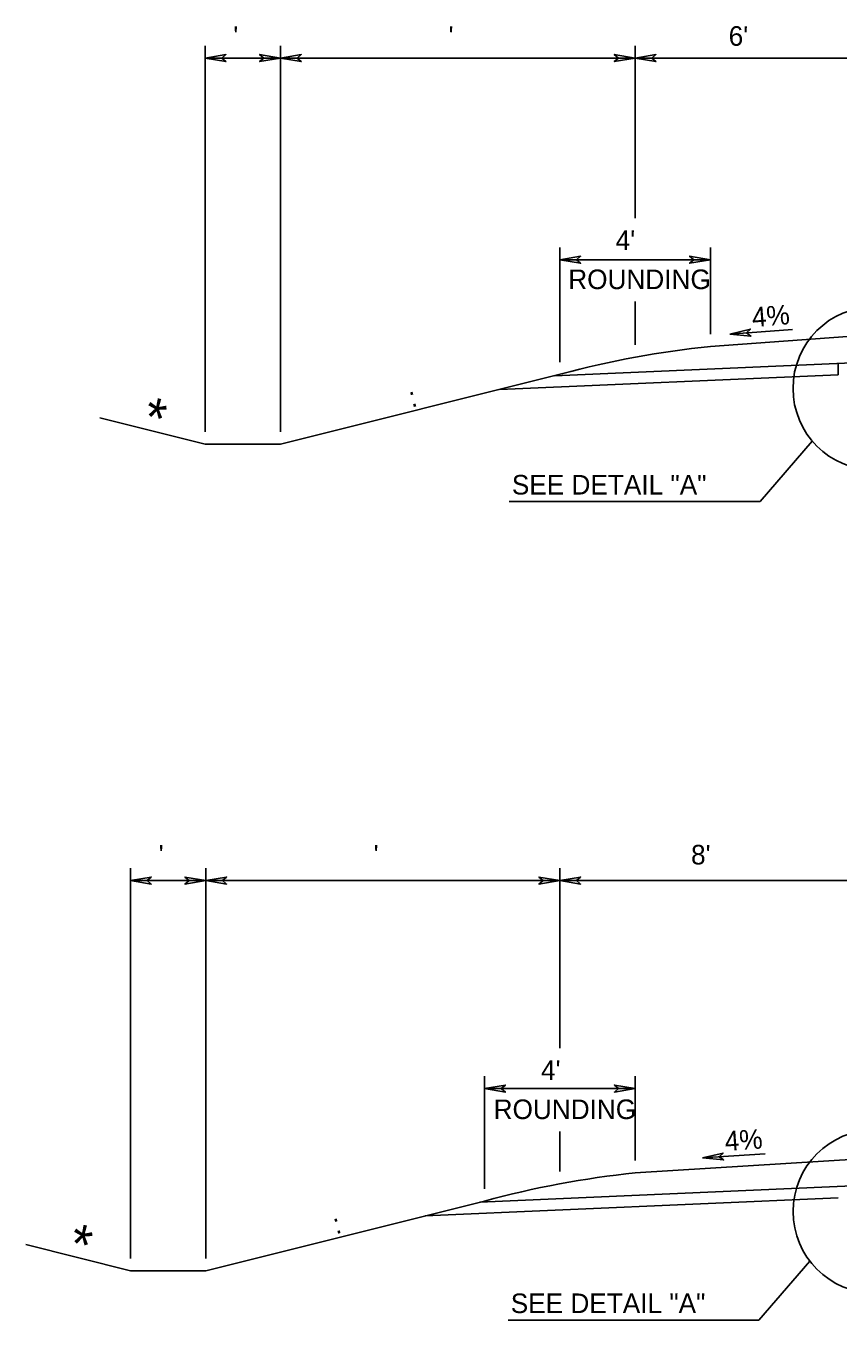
# Model space of a CAD drawing. Extents: x -540 to 1231, y -564 to 421.
# Drawn here: x -360 to -302, y 131.6 to 224.2 of the extents above; entities that cross this region are included whole.
import ezdxf

# ---------------------------------------------------------------- set-up
doc = ezdxf.new("R2010")
doc.units = 0
doc.layers.add('1', color=7, linetype='Continuous')
doc.layers.add('Des_ Drain_ Ftrs', color=7, linetype='Continuous')

msp = doc.modelspace()

# ---------------------------------------------------------------- linework, layer by layer
at = {"layer": '1'}
for p, q in [((-347.236, 195.118), (-347.236, 222.729)), ((-341.847, 195.118), (-341.847, 222.729)), ((-316.483, 210.408), (-316.483, 222.729)), ((-341.847, 221.849), (-347.236, 221.849)), ((-316.483, 221.849), (-341.847, 221.849)), ((-300.318, 221.849), (-316.483, 221.849)), ((-321.871, 200.111), (-321.871, 208.312)), ((-311.095, 202.117), (-311.095, 208.312)), ((-311.095, 207.432), (-321.871, 207.432)), ((-316.483, 201.34), (-316.483, 204.45)), ((-311.093, 201.238), (-300.327, 202.012)), ((-309.705, 202.115), (-305.219, 202.443)), ((-322.243, 199.138), (-273.377, 201.272)), ((-301.965, 200.022), (-301.965, 199.215)), ((-321.743, 199.263), (-341.847, 194.238)), ((-326.165, 198.158), (-301.965, 199.215)), ((-354.771, 196.122), (-347.236, 194.238)), ((-307.55, 190.143), (-303.81, 194.463)), ((-341.847, 194.238), (-347.236, 194.238)), ((-325.482, 190.143), (-307.55, 190.143)), ((-352.571, 136.034), (-352.571, 163.927)), ((-347.183, 136.034), (-347.183, 163.927)), ((-321.869, 151.054), (-321.869, 163.927)), ((-347.183, 163.047), (-352.571, 163.047)), ((-321.869, 163.047), (-347.183, 163.047)), ((-300.315, 163.047), (-321.869, 163.047)), ((-327.246, 141.018), (-327.246, 149.059)), ((-316.47, 143.027), (-316.47, 149.059)), ((-316.47, 148.179), (-327.246, 148.179)), ((-321.869, 142.248), (-321.869, 145.117)), ((-311.66, 143.227), (-307.171, 143.512)), ((-316.47, 142.147), (-300.32, 143.163)), ((-327.575, 140.056), (-273.374, 142.422)), ((-327.246, 140.138), (-347.183, 135.154)), ((-331.5, 139.074), (-301.962, 140.365)), ((-360.048, 137.023), (-352.571, 135.154)), ((-347.183, 135.154), (-352.571, 135.154)), ((-307.629, 131.623), (-303.981, 135.837)), ((-325.56, 131.623), (-307.629, 131.623))]:
    msp.add_line(p, q, dxfattribs=at)
for centre in [(-299.353, 198.235), (-299.35, 139.385)]:
    msp.add_circle(centre, 5.838, dxfattribs=at)
for centre, end in [((-304.211, 134.403), 105.12625), ((-309.587, 75.312), 105.23809)]:
    msp.add_arc(centre, 67.188, 95.87953, end, dxfattribs=at)
at = {"layer": 'Des_ Drain_ Ftrs'}
for points in [[(-347.236, 221.849), (-345.747, 221.6), (-346.042, 221.849), (-345.747, 222.097)], [(-341.847, 221.849), (-343.336, 221.6), (-343.041, 221.849), (-343.336, 222.097)], [(-341.847, 221.849), (-340.359, 221.6), (-340.654, 221.849), (-340.359, 222.097)], [(-316.483, 221.849), (-317.971, 221.6), (-317.676, 221.849), (-317.971, 222.097)], [(-316.483, 221.849), (-314.994, 221.6), (-315.289, 221.849), (-314.994, 222.097)], [(-321.871, 207.432), (-320.383, 207.183), (-320.678, 207.432), (-320.383, 207.68)], [(-311.095, 207.432), (-312.583, 207.183), (-312.288, 207.432), (-312.583, 207.68)], [(-309.705, 202.115), (-308.203, 201.974), (-308.515, 202.201), (-308.239, 202.469)], [(-352.571, 163.047), (-351.083, 162.799), (-351.378, 163.047), (-351.083, 163.296)], [(-347.183, 163.047), (-348.671, 162.799), (-348.376, 163.047), (-348.671, 163.296)], [(-347.183, 163.047), (-345.694, 162.799), (-345.989, 163.047), (-345.694, 163.296)], [(-321.869, 163.047), (-323.357, 162.799), (-323.062, 163.047), (-323.357, 163.296)], [(-321.869, 163.047), (-320.38, 162.799), (-320.675, 163.047), (-320.38, 163.296)], [(-327.246, 148.179), (-325.758, 147.931), (-326.053, 148.179), (-325.758, 148.427)], [(-316.47, 148.179), (-317.958, 147.931), (-317.663, 148.179), (-317.958, 148.427)], [(-311.66, 143.227), (-310.159, 143.072), (-310.469, 143.302), (-310.19, 143.568)]]:
    msp.add_lwpolyline(points, close=True, dxfattribs=at)

# ---------------------------------------------------------------- texts
at = {"layer": '1'}
for s, p in [(" '", (-345.736, 222.73)), ("  '", (-330.861, 222.73)), ("6'", (-309.791, 222.73)), ("4'", (-317.873, 208.132)), ('ROUNDING', (-321.262, 205.332)), ('SEE DETAIL "A"', (-325.296, 190.647)), (" '", (-351.072, 164.198)), ("  '", (-336.221, 164.198)), ("8'", (-312.482, 164.198)), ("4'", (-323.21, 148.795)), ('ROUNDING', (-326.599, 145.995)), ('SEE DETAIL "A"', (-325.375, 132.126))]:
    msp.add_text(s, height=1.4, dxfattribs=at).set_placement(p)
for s, height, rotation, p in [('4%', 1.4, 4.46565, (-308.078, 202.618)), ('*', 2.8, 347.15207, (-351.829, 194.935)), (' : ', 1.4, 14.22821, (-332.975, 196.738)), ('4%', 1.4, 3.91556, (-310.028, 143.714)), (' : ', 1.4, 14.22821, (-338.394, 137.633)), ('*', 2.8, 347.15207, (-357.136, 135.843))]:
    msp.add_text(s, height=height, rotation=rotation, dxfattribs=at).set_placement(p)

doc.saveas('drawing.dxf')
